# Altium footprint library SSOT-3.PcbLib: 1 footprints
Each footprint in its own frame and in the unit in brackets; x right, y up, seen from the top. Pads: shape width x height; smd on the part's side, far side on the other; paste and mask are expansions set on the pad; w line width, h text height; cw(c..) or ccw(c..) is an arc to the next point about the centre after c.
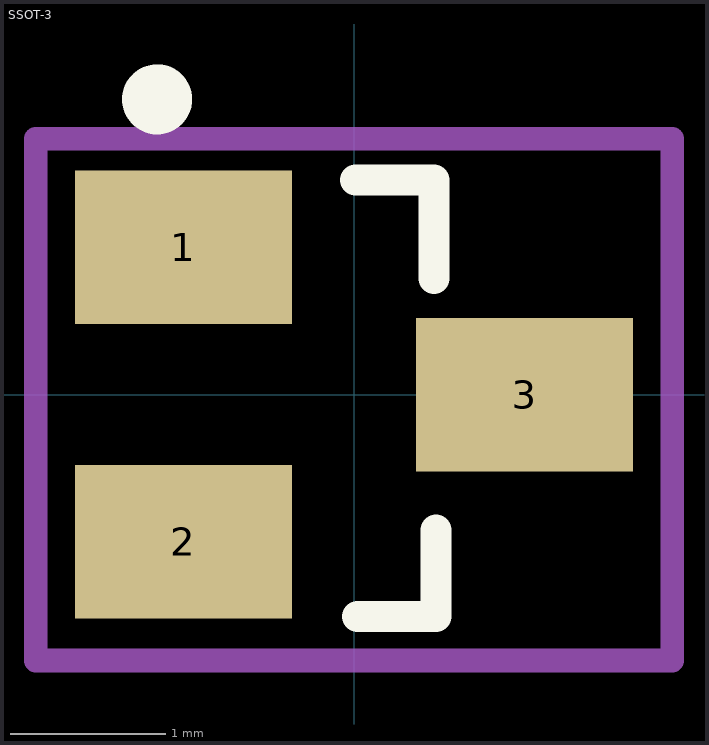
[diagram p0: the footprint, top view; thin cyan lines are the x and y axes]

## SSOT-3 [mil]
pads (3):
  rect 55x39 smd: 1(-43.31,37.4) 2(-43.31,-37.4) 3(43.31,0)
Top Overlay:
  circle w11.81: c-50,75 r3
  lines w7.87: 0.32,54.51 20.32,54.51 20.32,29.51 ; 0.83,-56.33 20.83,-56.33 20.83,-34.42
Mechanical 15:
  lines w6: -80.81,-67.5 -80.81,65 -47.3,65 23.7,65 80.81,65 80.81,-67.5 35.5,-67.5 -35.5,-67.5 -80.81,-67.5
3D body "User Library-ssot3.step": height 44.49, standoff 0, extent -65.73,-59.06 55.73,59.06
